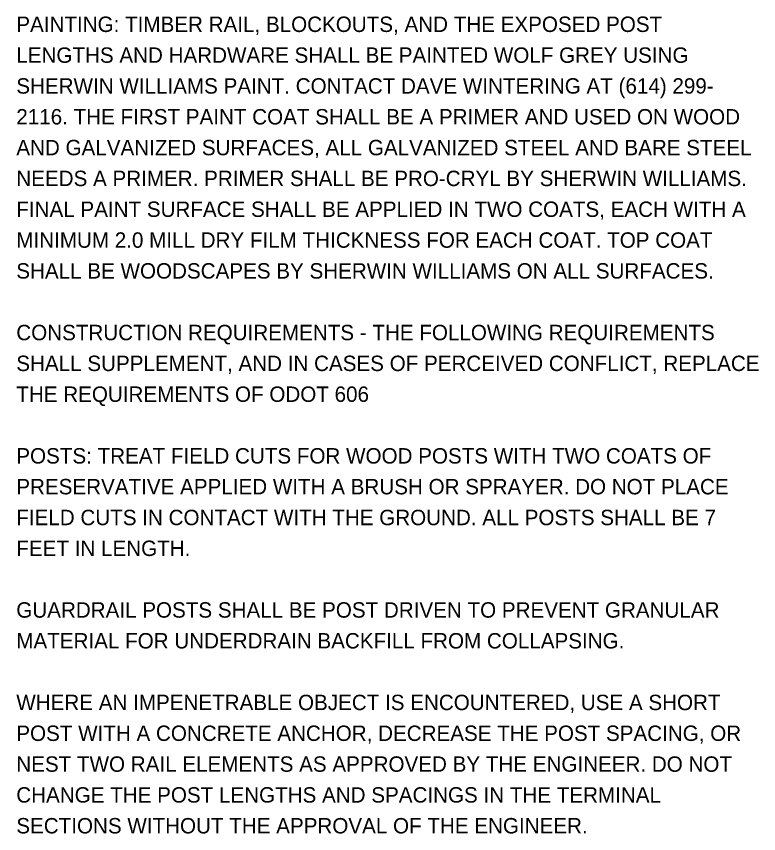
# Model space of a CAD drawing. Extents: x 0 to 84.3, y -13.4 to 22.
# Drawn here: x 77.6 to 84.35, y -1.68 to 5.74 of the extents above; entities that cross this region are included whole.
import ezdxf

# ---------------------------------------------------------------- set-up
doc = ezdxf.new("R2010")
doc.units = 0
doc.layers.add('SH_Text', color=7, linetype='Continuous')

msp = doc.modelspace()

# ---------------------------------------------------------------- texts
at = {"layer": 'SH_Text'}
for s, p in [('PAINTING: TIMBER RAIL, BLOCKOUTS, AND THE EXPOSED POST ', (77.6035, 5.6)), ('LENGTHS AND HARDWARE SHALL BE PAINTED WOLF GREY USING ', (77.6035, 5.32)), ('SHERWIN WILLIAMS PAINT. CONTACT DAVE WINTERING AT (614) 299-', (77.6035, 5.04)), ('2116. THE FIRST PAINT COAT SHALL BE A PRIMER AND USED ON WOOD ', (77.6035, 4.76)), ('AND GALVANIZED SURFACES, ALL GALVANIZED STEEL AND BARE STEEL ', (77.6035, 4.48)), ('NEEDS A PRIMER. PRIMER SHALL BE PRO-CRYL BY SHERWIN WILLIAMS. ', (77.6035, 4.2)), ('FINAL PAINT SURFACE SHALL BE APPLIED IN TWO COATS, EACH WITH A ', (77.6035, 3.92)), ('MINIMUM 2.0 MILL DRY FILM THICKNESS FOR EACH COAT. TOP COAT ', (77.6035, 3.64)), ('SHALL BE WOODSCAPES BY SHERWIN WILLIAMS ON ALL SURFACES.', (77.6035, 3.36)), ('CONSTRUCTION REQUIREMENTS - THE FOLLOWING REQUIREMENTS ', (77.6035, 2.8)), ('SHALL SUPPLEMENT, AND IN CASES OF PERCEIVED CONFLICT, REPLACE ', (77.6035, 2.52)), ('THE REQUIREMENTS OF ODOT 606', (77.6035, 2.24)), ('POSTS: TREAT FIELD CUTS FOR WOOD POSTS WITH TWO COATS OF ', (77.6035, 1.68)), ('PRESERVATIVE APPLIED WITH A BRUSH OR SPRAYER. DO NOT PLACE ', (77.6035, 1.4)), ('FIELD CUTS IN CONTACT WITH THE GROUND. ALL POSTS SHALL BE 7 ', (77.6035, 1.12)), ('FEET IN LENGTH.', (77.6035, 0.84)), ('GUARDRAIL POSTS SHALL BE POST DRIVEN TO PREVENT GRANULAR ', (77.6035, 0.28)), ('MATERIAL FOR UNDERDRAIN BACKFILL FROM COLLAPSING.', (77.6035, 0)), ('WHERE AN IMPENETRABLE OBJECT IS ENCOUNTERED, USE A SHORT ', (77.6035, -0.56)), ('POST WITH A CONCRETE ANCHOR, DECREASE THE POST SPACING, OR ', (77.6035, -0.84)), ('NEST TWO RAIL ELEMENTS AS APPROVED BY THE ENGINEER. DO NOT ', (77.6035, -1.12)), ('CHANGE THE POST LENGTHS AND SPACINGS IN THE TERMINAL ', (77.6035, -1.4)), ('SECTIONS WITHOUT THE APPROVAL OF THE ENGINEER.', (77.6035, -1.68))]:
    msp.add_text(s, height=0.14, dxfattribs=at).set_placement(p)

doc.saveas('drawing.dxf')
